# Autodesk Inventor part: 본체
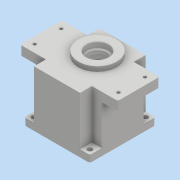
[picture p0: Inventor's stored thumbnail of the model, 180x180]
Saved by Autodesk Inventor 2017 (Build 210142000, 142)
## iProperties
Part Number: 본체
Material: 일반
Document SubType Name: Modeling
Designer: user
Density: 1 g/cm^3
Appearance: 기본값
Author: user
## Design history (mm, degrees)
sketch "스케치1"
  geometry: L1 (0, 60)-(140, 60); L2 (140, 60)-(140, 0); L3 (140, 0)-(0, 0); L4 (0, 0)-(0, 60); L5 (37, 77)-(103, 77); L6 (103, 77)-(103, -17); L7 (103, -17)-(37, -17); L8 (37, -17)-(37, 77); 1 further point
  constraints: 16 end point, 4 parallel, 2 horizontal, 2 perpendicular, 2 point on line
  dimensions: "d0" = 140 distance of L2.end L3.end; "d1" = 60 distance of L1.end L2.end; "d2" = 66 distance of L6.end L7.end; "d3" = 94 distance of L5.end L6.end; "d4" = 17 distance between parallel lines of L1 L5; "d5" = 37 distance between parallel lines of L4 L8
extrude "돌출1" new body sketch "스케치1" distance "d6" = 13; taper "d7" = 0 deg
sketch "스케치3"
  geometry: L1 (-37, 77)-(-103, 77) reference; L2 (-37, -17)-(-103, -17); L3 (-103, -17)-(-103, 77); L4 (-103, 77)-(-37, 77); L5 (-37, 77)-(-37, -17); L6 (-37, 0)-(0, 0) reference; L7 (-23, 0)-(-117, 0); L8 (-117, 0)-(-117, 60); L9 (-117, 60)-(-23, 60); L10 (-23, 60)-(-23, 0)
  constraints: 16 end point, 4 parallel, 2 horizontal, 2 perpendicular, 1 point on line
  dimensions: "d8" = 94 distance of L8.end L9.end; "d9" = 60 distance of L7.end L8.end; "d10" = 14 distance between parallel lines of L10 L5
extrude "돌출2" join sketch "스케치3" distance "d11" = 57; taper "d12" = 0 deg
sketch "스케치4"
  geometry: L1 (-23, -17)-(-117, -17); L2 (-117, -17)-(-117, 77); L3 (-117, 77)-(-23, 77); L4 (-23, 77)-(-23, -17); 3 further points
  constraints: 8 end point, 2 parallel, 2 point on line, 1 horizontal, 1 perpendicular
  dimensions: "d13" = 94 distance of L2.end L3.end; "d14" = 94 distance of L1.end L2.end
extrude "돌출3" join sketch "스케치4" distance "d15" = 10; taper "d16" = 0 deg
sketch "스케치5"
  geometry: L1 (37, -17)-(103, -17) reference; L2 (103, 77)-(37, 77) reference; C1 r 27.5 at (70, 41); 2 further points
  constraints: 1 centre point, 1 midpoint, 1 vertical alignment
  dimensions: "d17" = 55 diameter of C1; "d18" = 58 distance from line of L1 C1.centre
extrude "돌출4" join sketch "스케치5" distance "d19" = 7; taper "d20" = 0 deg
sketch "스케치6"
  geometry: C1 r 16 at (0, 0); C2 r 27.5 at (0, 0) reference; 1 further point
  constraints: 1 centre point, 1 concentric
  dimensions: "d21" = 32 diameter of C1
extrude "돌출5" cut sketch "스케치6" distance "d22" = 8.3; taper "d23" = 0 deg
sketch "스케치7"
  geometry: C1 r 12.5 at (0, 0); C2 r 16 at (0, 0) reference; 1 further point
  constraints: 1 centre point, 1 concentric
  dimensions: "d24" = 25 diameter of C1
extrude "돌출6" cut sketch "스케치7" distance "d25" = 4.7; taper "d26" = 0 deg
sketch "스케치8"
  geometry: C1 r 17.5 at (0, 0); C2 r 12.5 at (0, 0) reference; 1 further point
  constraints: 1 centre point, 1 concentric
  dimensions: "d27" = 35 diameter of C1
sketch "스케치9"
  geometry: L1 (0, 0)-(0, 60) reference; L2 (-23, 77)-(-117, 77) reference; C1 r 43 at (-70, 30)
  constraints: 1 centre point
  dimensions: "d28" = 86 diameter of C1; "d29" = 70 distance from line of L1 C1.centre; "d30" = 47 distance from line of C1.centre L2
extrude "돌출7" cut sketch "스케치9" distance "d31" = 9; taper "d32" = 0 deg
sketch "스케치10"
  geometry: C1 r 40 at (0, 0); C2 r 43 at (0, 0) reference; 1 further point
  constraints: 1 centre point, 1 concentric
  dimensions: "d33" = 80 diameter of C1
extrude "돌출8" cut sketch "스케치10" distance "d34" = 62; taper "d35" = 0 deg
sketch "스케치11"
  geometry: C1 r 40 at (0, 0) reference; C2 r 21 at (0, 11); C3 r 15 at (0, -20); 1 further point
  constraints: 2 centre point, 2 vertical alignment
  dimensions: "d36" = 42 diameter of C2; "d37" = 30 diameter of C3; "d38" = 11 distance of C1.centre C2.centre; "d39" = 20 distance of C3.centre C1.centre
extrude "돌출9" join sketch "스케치11" distance "d40" = 7; taper "d41" = 0 deg
extrude "돌출10" cut sketch "스케치8" distance "d42" = 57; taper "d43" = 0 deg
sketch "스케치12"
  geometry: C1 r 11 at (0, -20); A1 r 15 centre (0, -20) between (-8.978, -7.984) and (8.978, -7.984) reference; 1 further point
  constraints: 1 centre point, 1 concentric
  dimensions: "d44" = 22 diameter of C1
extrude "돌출11" cut sketch "스케치12" distance "d45" = 7; taper "d46" = 0 deg
sketch "스케치13"
  geometry: C1 r 9.5 at (0, 0); C2 r 11 at (0, 0) reference; 1 further point
  constraints: 1 centre point, 1 concentric
  dimensions: "d47" = 19 diameter of C1
extrude "돌출12" cut sketch "스케치13" distance "d48" = 3; taper "d49" = 0 deg
sketch "스케치14"
  geometry: L1 (103, 77)-(37, 77) reference; L2 (23, 77)-(23, 60) reference; 2 further points
  dimensions: "d50" = 7 distance from line of L1 point (30, 70); "d51" = 7 distance from line of L2 point (30, 70)
hole "구멍1" sketch "스케치14" at (30, 70) diameter "d52" = 7; stored, may be unused: countersink angle "d56" = 90 deg, drill point angle "d58" = 118 deg; dims "d53" = 6, "d54" = 4, "d55" = 2, "d57" = 8
sketch "스케치17"
  geometry: L1 (0, 60)-(-23, 60) reference; L2 (0, 0)-(0, 60) reference; 1 further point
  dimensions: "d65" = 49 distance from line of L1 point (-10, 11); "d66" = 10 distance from line of L2 point (-10, 11)
hole "구멍2" sketch "스케치17" at (-10, 11) diameter "d67" = 4.5; stored, may be unused: countersink angle "d71" = 90 deg, drill point angle "d73" = 118 deg; dims "d68" = 6, "d69" = 10, "d70" = 5, "d72" = 8
sketch "스케치20"
  geometry: A1 r 40 centre (0, 0) between (39.279, 7.559) and (39.279, -7.559) reference; A2 r 4 centre (36, 0) between (36.19, 3.995) and (36.19, -3.995); A3 r 3 centre (36.333, 6.992) between (36.19, 3.995) and (39.279, 7.559); A4 r 3 centre (36.333, -6.992) between (39.279, -7.559) and (36.19, -3.995); 1 further point
  constraints: 8 point on circle, 4 tangent, 3 centre point, 1 horizontal alignment
  dimensions: "d86" = 8 diameter of A2; "d87" = 36 distance of A1.centre A2.centre; "d88" = 3 radius of A3; "d89" = 3 radius of A4
extrude "돌출13" join sketch "스케치20" stored distance "d90" = 3; taper "d91" = 0 deg
hole "구멍3" diameter "d94" = 3.242; stored, may be unused: countersink angle "d98" = 90 deg, drill point angle "d100" = 118 deg; dims "d92" = 10, "d93" = 10, "d95" = 7, "d96" = 10, "d97" = 5, "d99" = 9
node "작업 평면1"
sketch "스케치21"
  geometry: L1 (-14, 80)-(80, 80) reference; L2 (66, 0)-(66, 70) reference; 2 further points
  constraints: 1 other
  dimensions: "d102" = 40 distance from line of L1 point (33, 40); "d103" = 33 distance from line of L2 point (33, 40)
feature "엠보싱1" sketch "스케치21" dims "d8" = 94, "d9" = 60, "d10" = 14, "d104" = 0.5, "d105" = 0
fillet "모깎기1" dims "d106" = 3
fillet "모깎기2" dims "d107" = 3
chamfer "모따기1" distance "d108" = 1; stored, may be unused: second distance "d109" = 2, angle "d110" = 45 deg
chamfer "모따기2" distance "d111" = 0.8; stored, may be unused: second distance "d112" = 2, angle "d113" = 30 deg
fillet "모깎기3" dims "d114" = 3
chamfer "모따기3" distance "d115" = 1; stored, may be unused: second distance "d116" = 2, angle "d117" = 30 deg
chamfer "모따기4" distance "d118" = 1; stored, may be unused: second distance "d119" = 2, angle "d120" = 30 deg
node "솔리드1"
pattern_linear "직사각형 패턴1" dims "d61" = -80
pattern_linear "직사각형 패턴2" dims "d64" = 80
pattern_linear "직사각형 패턴3" dims "d76" = 38
pattern_linear "직사각형 패턴4" dims "d79" = 120
mirror "미러1"
other parameters: "d101" = -47
